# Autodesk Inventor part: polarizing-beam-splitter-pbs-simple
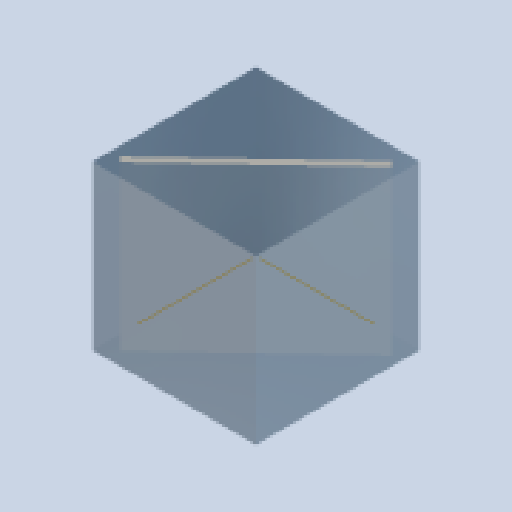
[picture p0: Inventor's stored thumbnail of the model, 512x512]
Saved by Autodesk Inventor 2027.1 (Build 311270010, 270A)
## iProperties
Created: 2026-07
Part Number: polarizing-beam-splitter-pbs-simple
Material: Generic
Document SubType Name: Modeling
Designer: dunge
Density: 1 g/cm^3
Appearance: Default
Author: dunge
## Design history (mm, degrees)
sketch "Sketch1"
  geometry: L1 (13.098, 13.251)-(13.97, 12.328); L2 (13.97, 12.328)-(-13.098, -13.251); L3 (-13.098, -13.251)-(-13.97, -12.328); L4 (-13.97, -12.328)-(13.098, 13.251); L5 (15.875, 15.875)-(-15.875, 15.875); L6 (-15.875, 15.875)-(-15.875, -15.875); L7 (-15.875, -15.875)-(15.875, -15.875); L8 (15.875, -15.875)-(15.875, 15.875); L9 (15.875, 15.875)-(-15.875, -15.875); L10 (-15.875, 15.875)-(15.875, -15.875); L11 (13.098, 13.251)-(-13.098, -13.251); L12 (13.97, 12.328)-(-13.97, -12.328); L13 (0, 9.79)-(0, -8.991); L14 (7.147, 0)-(-10.83, 0); 1 further point
  constraints: 28 end point, 4 parallel, 3 midpoint, 3 perpendicular, 2 horizontal, 1 point on line, 1 vertical
  dimensions: "CUBE_SIZE" = 31.75 distance of L5.end L6.end; "d2" = 1.27 distance of L2.end L3.end; "d6" = 1.905 distance from line of L8 L1.end
extrude "Extrusion1" new body sketch "Sketch1" stored distance "d4" = 31.75 (= CUBE_SIZE); taper "d5" = 0 deg
workpoint "Work Point1"
workaxis "Work Axis1"
workaxis "Work Axis2"
body "Solid1"
node "Finishes"
node "Finish3" dims "Finish3_Area" = 839.92385
node "Finish4" dims "Finish4_Area" = 244.5456
